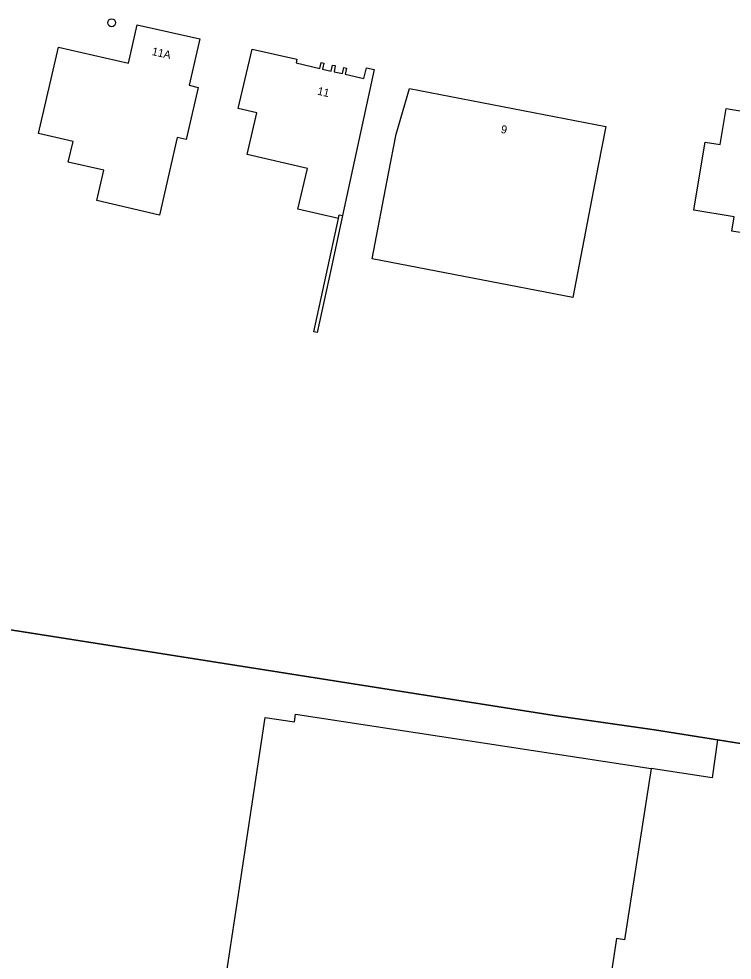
# Model space of a CAD drawing. Extents: x 161486 to 162249, y 379484 to 380829.
# Drawn here: x 161994.2 to 162083.3, y 380243.2 to 380360.8 of the extents above; entities that cross this region are included whole.
import ezdxf

# ---------------------------------------------------------------- set-up
doc = ezdxf.new("R2010")
doc.units = 0
for name, color, linetype in [('IMGEO_Boom', 7, 'Continuous'), ('IMGEO_Erf', 7, 'Continuous'), ('IMGEO_Grasland_agrarisch', 7, 'Continuous'), ('IMGEO_Hek', 7, 'Continuous'), ('IMGEO_Muur', 7, 'Continuous'), ('IMGEO_Pand', 7, 'Continuous'), ('IMGEO_Pand_nummerreeks', 7, 'Continuous')]:
    doc.layers.add(name, color=color, linetype=linetype)

msp = doc.modelspace()

# ---------------------------------------------------------------- linework, layer by layer
at = {"layer": 'IMGEO_Boom'}
msp.add_circle((162005.78, 380360.31), 0.489, dxfattribs=at)
at = {"layer": 'IMGEO_Erf'}
msp.add_lwpolyline([(162081.47, 380270.67), (162095.11, 380268.51), (162100.74, 380267.65), (162124.86, 380263.98)], dxfattribs=at)
at = {"layer": 'IMGEO_Grasland_agrarisch'}
for points in [[(161980.66, 380286.4), (162000, 380283.35), (162061.08, 380273.75), (162073.61, 380271.93), (162081.47, 380270.67)], [(162081.47, 380270.67), (162080.79, 380265.95), (162073.2, 380267.11)]]:
    msp.add_lwpolyline(points, dxfattribs=at)
at = {"layer": 'IMGEO_Hek'}
msp.add_lwpolyline([(162169.78, 380257.05), (162158.42, 380258.71), (162136.17, 380262.27), (162095.11, 380268.51), (162073.61, 380271.93), (162061.08, 380273.75), (162000, 380283.35), (161980.66, 380286.4)], dxfattribs=at)
at = {"layer": 'IMGEO_Muur'}
msp.add_lwpolyline([(162034.62, 380336.21), (162033.19, 380329.6), (162031.45, 380321.6), (162031.04, 380321.69), (162034.11, 380335.83)], dxfattribs=at)
at = {"layer": 'IMGEO_Pand'}
for points in [[(161999.13, 380357.27), (162007.87, 380355.26), (162008.97, 380360.06), (162016.78, 380358.28), (162015.46, 380352.49), (162016.58, 380352.23), (162015.1, 380345.73), (162013.98, 380345.98), (162011.77, 380336.28), (162003.92, 380338.08), (162004.8, 380341.87), (162000.36, 380342.89), (162000.96, 380345.47), (161996.64, 380346.46), (161999.13, 380357.27)], [(162034.11, 380335.83), (162029.06, 380337.01), (162030.24, 380342.1), (162022.72, 380343.86), (162023.93, 380349.06), (162021.58, 380349.61), (162023.32, 380357.02), (162028.92, 380355.74), (162028.82, 380355.32), (162031.79, 380354.61), (162031.97, 380355.35), (162032.3, 380355.27), (162032.13, 380354.52), (162033.21, 380354.28), (162033.38, 380355.02), (162033.71, 380354.95), (162033.57, 380354.19), (162034.62, 380353.95), (162034.8, 380354.7), (162035.14, 380354.62), (162034.97, 380353.87), (162037.3, 380353.34), (162037.61, 380354.67), (162038.59, 380354.46), (162034.62, 380336.21)], [(162042.98, 380352.09), (162067.51, 380347.36), (162066.56, 380342.45), (162063.38, 380325.96), (162038.33, 380330.79), (162040.39, 380341.46), (162041.33, 380346.37), (162042.98, 380352.09)], [(162079.92, 380345.39), (162081.82, 380345.08), (162082.56, 380349.59), (162091.88, 380348.07), (162090.8, 380341.46), (162094.77, 380340.81), (162100.58, 380339.86), (162098.81, 380329.06), (162095.3, 380329.63), (162096.02, 380334.01), (162093.72, 380334.38), (162090.21, 380334.96), (162087.17, 380335.46), (162086.87, 380333.66), (162083.25, 380334.25), (162083.54, 380336.05), (162078.52, 380336.87), (162079.1, 380340.44), (162079.92, 380345.39)], [(162034.11, 380335.83), (162034.22, 380336.3), (162034.62, 380336.21)], [(162019.68, 380238.5), (162021.43, 380250), (162024.98, 380273.48), (162028.62, 380272.92), (162028.77, 380273.91), (162073.2, 380267.11)], [(162073.2, 380267.11), (162070.53, 380250), (162069.86, 380245.71), (162068.87, 380245.86), (162067.82, 380238.99)]]:
    msp.add_lwpolyline(points, dxfattribs=at)

# ---------------------------------------------------------------- texts
at = {"layer": 'IMGEO_Pand_nummerreeks'}
for s, rotation, p in [('11A', 347.1411, (162010.74, 380356.29)), ('11', 346.8165, (162031.41, 380351.34)), ('9', 349.0801, (162054.35, 380346.56))]:
    msp.add_text(s, height=1, rotation=rotation, dxfattribs=at).set_placement(p)

doc.saveas('drawing.dxf')
